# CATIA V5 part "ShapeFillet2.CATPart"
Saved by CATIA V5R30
Part number: Part1
Bounding box of the stored display mesh (mm): x 2636.929 to 2658.584, y 475.412 to 576.341, z 2218.145 to 2468.369
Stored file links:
  D:\PROJECTS\CATIA V56R 2020\Resources\Parts File\c17_catia_v6_6r2020_prt\ShapeFillet2.CATPart
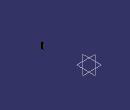
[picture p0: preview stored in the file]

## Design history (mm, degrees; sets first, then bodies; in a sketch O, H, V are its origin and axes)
Set1
  DatumSurface1 to DatumSurface4
  Fillet1: type BiTangent, Element1 DatumSurface2, Element2 DatumSurface1, Radius 3
  Trim1: Element1 DatumSurface3, Element2 Fillet1
  Fillet2: type BiTangent, Element1 DatumSurface4, Element2 Trim1, Radius 4, FacesToKeep face of Fillet1
Body1 (main body)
